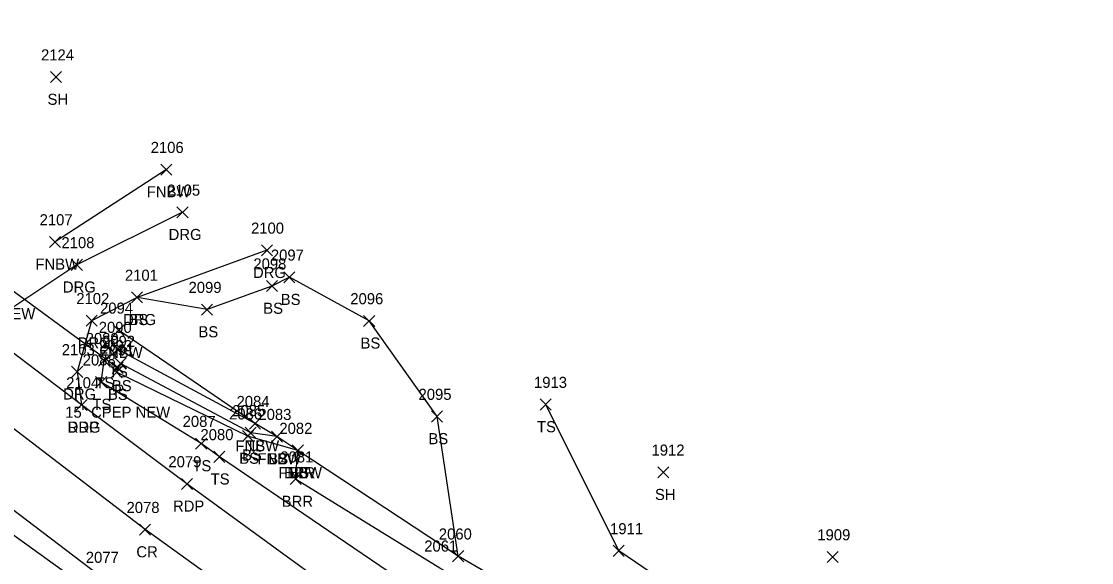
# Model space of a CAD drawing. Extents: x 1415642 to 1422021, y 544543 to 547232.
# Drawn here: x 1415773.3 to 1415966.4, y 547093.4 to 547191 of the extents above; entities that cross this region are included whole.
import ezdxf

# ---------------------------------------------------------------- set-up
doc = ezdxf.new("R2010")
doc.units = 0
for name, color, linetype in [('D_A', 7, 'Continuous'), ('D_C', 7, 'Continuous'), ('D_I', 7, 'Continuous'), ('D_TIC', 7, 'Continuous'), ('DCP', 7, 'Continuous'), ('L_A', 7, 'Continuous'), ('L_I', 7, 'Continuous'), ('L_TIC', 7, 'Continuous'), ('LABL', 7, 'Continuous'), ('LELB', 7, 'Continuous'), ('LFNC', 7, 'Continuous'), ('P_A', 7, 'Continuous'), ('P_I', 7, 'Continuous'), ('P_TIC', 7, 'Continuous'), ('PET', 7, 'Continuous'), ('PRC', 7, 'Continuous'), ('R_A', 7, 'Continuous'), ('R_I', 7, 'Continuous'), ('R_TIC', 7, 'Continuous'), ('RDG', 7, 'Continuous')]:
    doc.layers.add(name, color=color, linetype=linetype)

msp = doc.modelspace()

# ---------------------------------------------------------------- linework, layer by layer
at = {"layer": 'D_TIC'}
for points in [[(1415789.67, 547127.55), (1415791.67, 547129.55)], [(1415791.67, 547127.55), (1415789.67, 547129.55)]]:
    msp.add_lwpolyline(points, dxfattribs=at)
at = {"layer": 'DCP'}
msp.add_lwpolyline([(1415790.67, 547128.55), (1415766.34, 547146.32)], dxfattribs=at)
msp.add_lwpolyline([(1415790.67, 547128.55), (1415766.34, 547146.32)], dxfattribs=at)
at = {"layer": 'L_TIC'}
for points in [[(1415778.53, 547180), (1415780.53, 547182)], [(1415780.53, 547180), (1415778.53, 547182)], [(1415798.46, 547163.31), (1415800.46, 547165.31)], [(1415800.46, 547163.31), (1415798.46, 547165.31)], [(1415778.37, 547150.26), (1415780.37, 547152.26)], [(1415780.37, 547150.26), (1415778.37, 547152.26)], [(1415820.65, 547143.89), (1415822.65, 547145.89)], [(1415822.65, 547143.89), (1415820.65, 547145.89)], [(1415817.49, 547142.3), (1415819.49, 547144.3)], [(1415819.49, 547142.3), (1415817.49, 547144.3)], [(1415793.18, 547140.26), (1415795.18, 547142.26)], [(1415795.18, 547140.26), (1415793.18, 547142.26)], [(1415805.8, 547138.06), (1415807.8, 547140.06)], [(1415807.8, 547138.06), (1415805.8, 547140.06)], [(1415835.04, 547136.02), (1415837.04, 547138.02)], [(1415837.04, 547136.02), (1415835.04, 547138.02)], [(1415789.83, 547134.32), (1415791.83, 547136.32)], [(1415791.83, 547134.32), (1415789.83, 547136.32)], [(1415789.68, 547130.85), (1415791.68, 547132.85)], [(1415791.68, 547130.85), (1415789.68, 547132.85)], [(1415789.68, 547130.85), (1415791.68, 547132.85)], [(1415791.68, 547130.85), (1415789.68, 547132.85)], [(1415787.24, 547128.84), (1415789.24, 547130.84)], [(1415789.24, 547128.84), (1415787.24, 547130.84)], [(1415790.18, 547128.33), (1415792.18, 547130.33)], [(1415792.18, 547128.33), (1415790.18, 547130.33)], [(1415790.18, 547128.33), (1415792.18, 547130.33)], [(1415792.18, 547128.33), (1415790.18, 547130.33)], [(1415789.47, 547126.76), (1415791.47, 547128.76)], [(1415791.47, 547126.76), (1415789.47, 547128.76)], [(1415786.7, 547124.97), (1415788.7, 547126.97)], [(1415788.7, 547124.97), (1415786.7, 547126.97)], [(1415866.9, 547120.93), (1415868.9, 547122.93)], [(1415868.9, 547120.93), (1415866.9, 547122.93)], [(1415814.46, 547117.48), (1415816.46, 547119.48)], [(1415816.46, 547117.48), (1415814.46, 547119.48)], [(1415814.46, 547117.48), (1415816.46, 547119.48)], [(1415816.46, 547117.48), (1415814.46, 547119.48)], [(1415847.29, 547118.77), (1415849.29, 547120.77)], [(1415849.29, 547118.77), (1415847.29, 547120.77)], [(1415813.67, 547115.83), (1415815.67, 547117.83)], [(1415815.67, 547115.83), (1415813.67, 547117.83)], [(1415804.73, 547113.89), (1415806.73, 547115.89)], [(1415806.73, 547113.89), (1415804.73, 547115.89)], [(1415813.17, 547115.24), (1415815.17, 547117.24)], [(1415815.17, 547115.24), (1415813.17, 547117.24)], [(1415818.4, 547115.14), (1415820.4, 547117.14)], [(1415820.4, 547115.14), (1415818.4, 547117.14)], [(1415818.4, 547115.14), (1415820.4, 547117.14)], [(1415820.4, 547115.14), (1415818.4, 547117.14)], [(1415808.03, 547111.5), (1415810.03, 547113.5)], [(1415810.03, 547111.5), (1415808.03, 547113.5)], [(1415822.18, 547112.63), (1415824.18, 547114.63)], [(1415824.18, 547112.63), (1415822.18, 547114.63)], [(1415822.18, 547112.63), (1415824.18, 547114.63)], [(1415824.18, 547112.63), (1415822.18, 547114.63)], [(1415822.18, 547112.63), (1415824.18, 547114.63)], [(1415824.18, 547112.63), (1415822.18, 547114.63)], [(1415888.11, 547108.71), (1415890.11, 547110.71)], [(1415890.11, 547108.71), (1415888.11, 547110.71)], [(1415821.78, 547107.48), (1415823.78, 547109.48)], [(1415823.78, 547107.48), (1415821.78, 547109.48)], [(1415880.06, 547094.53), (1415882.06, 547096.53)], [(1415882.06, 547094.53), (1415880.06, 547096.53)], [(1415851.09, 547093.57), (1415853.09, 547095.57)], [(1415853.09, 547093.57), (1415851.09, 547095.57)], [(1415851.09, 547093.57), (1415853.09, 547095.57)], [(1415853.09, 547093.57), (1415851.09, 547095.57)], [(1415918.67, 547093.43), (1415920.67, 547095.43)], [(1415920.67, 547093.43), (1415918.67, 547095.43)]]:
    msp.add_lwpolyline(points, dxfattribs=at)
at = {"layer": 'LABL'}
for points in [[(1415954.88, 547028.96), (1415919.29, 547048.67), (1415882.22, 547073.43), (1415848.8, 547092.4), (1415822.78, 547108.48), (1415823.18, 547113.64)], [(1415954.88, 547028.97), (1415919.29, 547048.66), (1415882.22, 547073.42), (1415848.8, 547092.4), (1415822.78, 547108.48), (1415823.18, 547113.63)]]:
    msp.add_lwpolyline(points, dxfattribs=at)
at = {"layer": 'LELB'}
for points in [[(1415852.09, 547094.57), (1415848.29, 547119.77), (1415836.04, 547137.02), (1415821.65, 547144.89), (1415818.49, 547143.3), (1415806.8, 547139.06), (1415794.18, 547141.26)], [(1415852.09, 547094.57), (1415848.29, 547119.77), (1415836.03, 547137.02), (1415821.65, 547144.89), (1415818.49, 547143.3), (1415806.8, 547139.06), (1415794.18, 547141.26)], [(1416091.47, 546896.23), (1416067.28, 546915.33), (1416036.7, 546941.48), (1416008.25, 546963.65), (1415975.6, 546988.56), (1415942.26, 547013.09), (1415909.12, 547036.86), (1415872.92, 547061.56), (1415845.5, 547087.74), (1415809.03, 547112.5), (1415805.73, 547114.89), (1415787.7, 547125.97), (1415788.24, 547129.84), (1415790.68, 547131.85)], [(1416091.47, 546896.23), (1416067.28, 546915.33), (1416036.71, 546941.48), (1416008.26, 546963.65), (1415975.6, 546988.56), (1415942.26, 547013.09), (1415909.12, 547036.86), (1415872.92, 547061.56), (1415845.5, 547087.74), (1415809.04, 547112.5), (1415805.73, 547114.9), (1415787.7, 547125.97), (1415788.24, 547129.84), (1415790.68, 547131.85)], [(1415815.46, 547118.48), (1415790.68, 547131.85)], [(1415815.45, 547118.48), (1415790.68, 547131.85)], [(1415823.18, 547113.63), (1415814.17, 547116.24), (1415790.47, 547127.76), (1415791.18, 547129.33)], [(1415823.18, 547113.64), (1415814.17, 547116.24), (1415790.47, 547127.76), (1415791.19, 547129.33)], [(1415819.4, 547116.14), (1415814.67, 547116.83), (1415791.18, 547129.33)], [(1415819.41, 547116.14), (1415814.67, 547116.83), (1415791.19, 547129.33)], [(1416157.94, 546955.38), (1416155.92, 546957.27), (1416135.55, 546960.79), (1416132.49, 546973.78), (1416110.9, 546979.13), (1416081.52, 546992.2), (1416051.18, 547012.47), (1416023.77, 547025.27), (1415981.89, 547041.76), (1415959.36, 547046.67), (1415931.91, 547061.5), (1415911.94, 547074.57), (1415881.06, 547095.53), (1415867.9, 547121.94)], [(1416157.94, 546955.38), (1416155.92, 546957.27), (1416135.55, 546960.79), (1416132.49, 546973.77), (1416110.9, 546979.12), (1416081.52, 546992.2), (1416051.18, 547012.47), (1416023.76, 547025.27), (1415981.89, 547041.76), (1415959.36, 547046.67), (1415931.91, 547061.5), (1415911.93, 547074.57), (1415881.06, 547095.53), (1415867.9, 547121.93)], [(1415979.27, 546932.57), (1415964.6, 546940.59), (1415957.63, 546956.7), (1415934.73, 546972.98), (1415912.21, 546991.17), (1415886.95, 547011.09), (1415854.08, 547036.67), (1415824.18, 547059.44), (1415786.82, 547087.62), (1415741.01, 547120.53)], [(1415979.28, 546932.57), (1415964.61, 546940.59), (1415957.63, 546956.7), (1415934.74, 546972.98), (1415912.22, 546991.17), (1415886.96, 547011.09), (1415854.08, 547036.67), (1415824.19, 547059.44), (1415786.82, 547087.62), (1415741.01, 547120.53)]]:
    msp.add_lwpolyline(points, dxfattribs=at)
at = {"layer": 'LFNC'}
for points in [[(1415799.46, 547164.31), (1415779.37, 547151.26)], [(1415799.45, 547164.31), (1415779.37, 547151.26)], [(1416067.58, 546984.06), (1416031.2, 546999.34), (1415996.11, 547015.1), (1415957.45, 547035.03), (1415922.34, 547052.78), (1415883.85, 547076.17), (1415852.09, 547094.57), (1415823.18, 547113.63), (1415819.4, 547116.14), (1415815.46, 547118.48), (1415790.83, 547135.32)], [(1416067.58, 546984.06), (1416031.2, 546999.34), (1415996.12, 547015.09), (1415957.45, 547035.03), (1415922.34, 547052.78), (1415883.85, 547076.17), (1415852.09, 547094.57), (1415823.18, 547113.64), (1415819.41, 547116.14), (1415815.45, 547118.48), (1415790.83, 547135.32)]]:
    msp.add_lwpolyline(points, dxfattribs=at)
at = {"layer": 'P_TIC'}
for points in [[(1415783.15, 547120.85), (1415785.15, 547122.85)], [(1415785.15, 547120.85), (1415783.15, 547122.85)], [(1415802.16, 547106.61), (1415804.16, 547108.61)], [(1415804.16, 547106.61), (1415802.16, 547108.61)], [(1415794.61, 547098.36), (1415796.61, 547100.36)], [(1415796.61, 547098.36), (1415794.61, 547100.36)]]:
    msp.add_lwpolyline(points, dxfattribs=at)
at = {"layer": 'PET'}
for points in [[(1415969.06, 546981.93), (1415936.64, 547006.92), (1415904.27, 547031.49), (1415869.9, 547057.78), (1415840.56, 547080.38), (1415803.16, 547107.61), (1415784.15, 547121.85), (1415763.35, 547137.62), (1415738.26, 547155), (1415710.8, 547176.64), (1415691.9, 547191.05)], [(1415969.07, 546981.93), (1415936.65, 547006.92), (1415904.27, 547031.49), (1415869.9, 547057.78), (1415840.56, 547080.38), (1415803.16, 547107.61), (1415784.15, 547121.85), (1415763.35, 547137.62), (1415738.26, 547155), (1415710.8, 547176.64), (1415691.9, 547191.04)], [(1415982.21, 546942.39), (1415954.4, 546964.56), (1415923.45, 546987.94), (1415890.93, 547013.5), (1415855.69, 547039.7), (1415826.51, 547062.15), (1415788.27, 547090.37), (1415749.29, 547120.02), (1415723.83, 547138.72), (1415697.43, 547158.88), (1415677.46, 547174.08)], [(1415982.21, 546942.39), (1415954.4, 546964.56), (1415923.45, 546987.94), (1415890.93, 547013.5), (1415855.69, 547039.7), (1415826.51, 547062.15), (1415788.27, 547090.37), (1415749.28, 547120.03), (1415723.83, 547138.72), (1415697.43, 547158.88), (1415677.46, 547174.08)]]:
    msp.add_lwpolyline(points, dxfattribs=at)
at = {"layer": 'PRC'}
for points in [[(1415989.92, 546951.68), (1415962.46, 546973.18), (1415930.15, 546997.68), (1415898.02, 547022.56), (1415862.93, 547049.07), (1415833.82, 547071.85), (1415795.61, 547099.36), (1415756.73, 547129.15), (1415731.28, 547147.85), (1415704.22, 547168.12), (1415684.99, 547182.73)], [(1415989.92, 546951.67), (1415962.46, 546973.18), (1415930.15, 546997.68), (1415898.02, 547022.56), (1415862.93, 547049.07), (1415833.81, 547071.85), (1415795.61, 547099.36), (1415756.73, 547129.15), (1415731.28, 547147.85), (1415704.22, 547168.13), (1415684.99, 547182.72)]]:
    msp.add_lwpolyline(points, dxfattribs=at)
at = {"layer": 'R_TIC'}
for points in [[(1415801.37, 547155.61), (1415803.37, 547157.61)], [(1415803.37, 547155.61), (1415801.37, 547157.61)], [(1415816.59, 547148.75), (1415818.59, 547150.75)], [(1415818.59, 547148.75), (1415816.59, 547150.75)], [(1415782.3, 547146.13), (1415784.3, 547148.13)], [(1415784.3, 547146.13), (1415782.3, 547148.13)], [(1415793.18, 547140.26), (1415795.18, 547142.26)], [(1415795.18, 547140.26), (1415793.18, 547142.26)], [(1415784.98, 547136.05), (1415786.98, 547138.05)], [(1415786.98, 547136.05), (1415784.98, 547138.05)], [(1415782.36, 547126.83), (1415784.36, 547128.83)], [(1415784.36, 547126.83), (1415782.36, 547128.83)], [(1415783.15, 547120.85), (1415785.15, 547122.85)], [(1415785.15, 547120.85), (1415783.15, 547122.85)]]:
    msp.add_lwpolyline(points, dxfattribs=at)
at = {"layer": 'RDG'}
for points in [[(1415802.37, 547156.61), (1415783.3, 547147.13), (1415769.6, 547137.98), (1415763.35, 547137.62)], [(1415802.37, 547156.61), (1415783.3, 547147.13), (1415769.6, 547137.98), (1415763.35, 547137.62)], [(1415817.59, 547149.75), (1415794.18, 547141.26), (1415785.98, 547137.05), (1415783.36, 547127.83), (1415784.15, 547121.85)], [(1415817.59, 547149.75), (1415794.18, 547141.26), (1415785.98, 547137.05), (1415783.36, 547127.83), (1415784.15, 547121.85)]]:
    msp.add_lwpolyline(points, dxfattribs=at)

# ---------------------------------------------------------------- texts
at = {"layer": 'D_A'}
msp.add_text('P', height=2, dxfattribs=at).set_placement((1415790.05, 547123.55))
at = {"layer": 'D_C'}
for p in [(1415756.88, 547137.32), (1415781.21, 547119.55)]:
    msp.add_text('15" CPEP NEW', height=2, dxfattribs=at).set_placement(p)
at = {"layer": 'D_I'}
msp.add_text('2093', height=2, dxfattribs=at).set_placement((1415787.34, 547131.55))
at = {"layer": 'L_A'}
for s, p in [('SH', (1415778.02, 547176)), ('FNBW', (1415795.93, 547159.31)), ('FNBW', (1415775.84, 547146.26)), ('BS', (1415820.09, 547139.89)), ('BS', (1415816.93, 547138.3)), ('BS', (1415792.62, 547136.26)), ('BS', (1415805.24, 547134.06)), ('BS', (1415834.48, 547132.02)), ('FNBW', (1415787.3, 547130.32)), ('TS', (1415789.09, 547126.85)), ('TS', (1415789.09, 547126.85)), ('TS', (1415786.65, 547124.84)), ('BS', (1415789.62, 547124.33)), ('BS', (1415789.62, 547124.33)), ('BS', (1415788.91, 547122.76)), ('TS', (1415786.11, 547120.97)), ('TS', (1415866.31, 547116.93)), ('FNBW', (1415811.93, 547113.48)), ('TS', (1415813.87, 547113.48)), ('BS', (1415846.73, 547114.77)), ('BS', (1415813.11, 547111.83)), ('TS', (1415804.14, 547109.89)), ('BS', (1415812.61, 547111.24)), ('FNBW', (1415815.88, 547111.14)), ('BS', (1415817.84, 547111.14)), ('FNBW', (1415819.65, 547108.63)), ('BRR', (1415820.67, 547108.63)), ('BS', (1415821.62, 547108.63)), ('TS', (1415807.44, 547107.5)), ('SH', (1415887.6, 547104.71)), ('BRR', (1415820.27, 547103.48))]:
    msp.add_text(s, height=2, dxfattribs=at).set_placement(p)
at = {"layer": 'L_I'}
for s, p in [('2124', (1415776.84, 547184)), ('2106', (1415796.63, 547167.31)), ('2107', (1415776.59, 547154.26)), ('2098', (1415815.15, 547146.3)), ('2097', (1415818.31, 547147.89)), ('2101', (1415791.98, 547144.26)), ('2099', (1415803.46, 547142.06)), ('2096', (1415832.64, 547140.02)), ('2094', (1415787.49, 547138.32)), ('2090', (1415787.26, 547134.85)), ('2090', (1415787.26, 547134.85)), ('2089', (1415784.9, 547132.84)), ('2091', (1415787.7, 547130.76)), ('2092', (1415787.85, 547132.33)), ('2092', (1415787.85, 547132.33)), ('2088', (1415784.36, 547128.97)), ('1913', (1415865.78, 547124.93)), ('2084', (1415812.12, 547121.48)), ('2084', (1415812.12, 547121.48)), ('2095', (1415844.95, 547122.77)), ('2086', (1415810.77, 547119.24)), ('2085', (1415811.33, 547119.83)), ('2087', (1415802.39, 547117.89)), ('2083', (1415816.06, 547119.14)), ('2083', (1415816.06, 547119.14)), ('2080', (1415805.61, 547115.5)), ('2082', (1415819.84, 547116.63)), ('2082', (1415819.84, 547116.63)), ('2082', (1415819.84, 547116.63)), ('2081', (1415820.01, 547111.48)), ('1912', (1415886.98, 547112.71)), ('1911', (1415879.5, 547098.53)), ('2060', (1415848.61, 547097.57)), ('2060', (1415848.61, 547097.57)), ('1909', (1415916.89, 547097.43)), ('2061', (1415845.98, 547095.4)), ('2061', (1415845.98, 547095.4))]:
    msp.add_text(s, height=2, dxfattribs=at).set_placement(p)
at = {"layer": 'P_A'}
for s, p in [('RDP', (1415781.64, 547116.85)), ('RDP', (1415800.65, 547102.61)), ('CR', (1415794.04, 547094.36))]:
    msp.add_text(s, height=2, dxfattribs=at).set_placement(p)
at = {"layer": 'P_I'}
for s, p in [('2104', (1415781.38, 547124.85)), ('2079', (1415799.82, 547110.61)), ('2078', (1415792.27, 547102.36)), ('2077', (1415784.93, 547093.37))]:
    msp.add_text(s, height=2, dxfattribs=at).set_placement(p)
at = {"layer": 'R_A'}
for p in [(1415799.86, 547151.61), (1415815.08, 547144.75), (1415780.79, 547142.13), (1415791.67, 547136.26), (1415783.47, 547132.05), (1415780.85, 547122.83), (1415781.64, 547116.85)]:
    msp.add_text('DRG', height=2, dxfattribs=at).set_placement(p)
at = {"layer": 'R_I'}
for s, p in [('2105', (1415799.6, 547159.61)), ('2100', (1415814.73, 547152.75)), ('2108', (1415780.53, 547150.13)), ('2101', (1415791.98, 547144.26)), ('2102', (1415783.21, 547140.05)), ('2103', (1415780.59, 547130.83)), ('2104', (1415781.38, 547124.85))]:
    msp.add_text(s, height=2, dxfattribs=at).set_placement(p)

doc.saveas('drawing.dxf')
